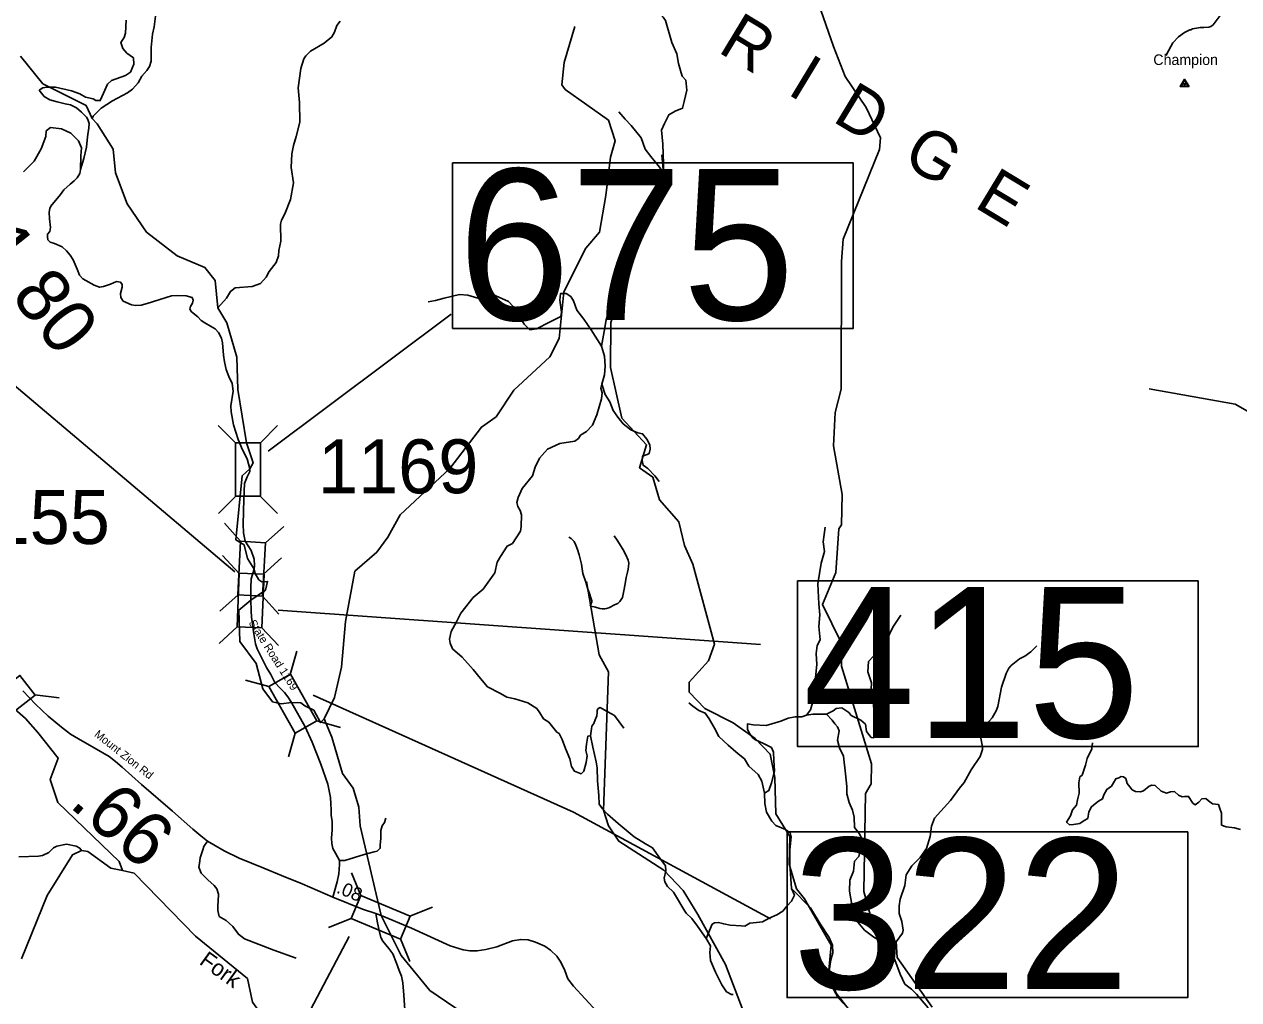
# Model space of a CAD drawing. Extents: x 1248089 to 1457196, y 820910 to 988753.
# Drawn here: x 1288997 to 1300259, y 874876 to 883926 of the extents above; entities that cross this region are included whole.
import ezdxf

# ---------------------------------------------------------------- set-up
doc = ezdxf.new("R2010")
doc.units = 0
for name, color, linetype in [('Exist Geographical Mountain Summit Label', 7, 'Continuous'), ('Exist Hydrographic Creek Single Shore', 7, 'Continuous'), ('Exist Hydrographic Misc Water Feature', 7, 'Continuous'), ('Exist Road Non-System Type 51', 7, 'Continuous'), ('Exist Road Secondary Structure Standard Bridge CELL', 7, 'Continuous'), ('Exist Road Secondary Structure Standard Bridge Number Label', 7, 'Continuous'), ('Exist Road Secondary Type 41 Attributed', 7, 'Continuous'), ('Exist Road Secondary Type 51 Attributed', 7, 'Continuous'), ('Exist Road Secondary Type 51 Label', 7, 'Continuous'), ('Exist Survey Geodetic Marker CELL', 7, 'Continuous'), ('Exist Survey Geodetic Marker Label', 7, 'Continuous'), ('Prop GRAU CAT1 Cell', 7, 'Continuous'), ('Prop Lane Lines', 7, 'Continuous'), ('Scratch_Level_4', 7, 'Continuous')]:
    doc.layers.add(name, color=color, linetype=linetype)

msp = doc.modelspace()

# ---------------------------------------------------------------- linework, layer by layer
at = {"layer": 'Exist Hydrographic Creek Single Shore'}
for points in [[(1291089, 879802), (1291119, 879858), (1291056, 880043), (1290977, 880537), (1290967, 880836), (1290875, 881156), (1290791, 881295), (1290768, 881549), (1290671, 881669), (1290415, 881776), (1290129, 881998), (1289952, 882261), (1289842, 882549), (1289822, 882766), (1289673, 883001), (1289627, 883052), (1289570, 883171), (1289170, 883373), (1288960, 883630)], [(1300406, 880298), (1300225, 880400), (1299427, 880544)], [(1291127, 878871), (1291067, 878970), (1291036, 879096), (1290959, 879142), (1291017, 879738), (1291089, 879802)], [(1291098, 878582), (1291235, 878677), (1291253, 878757), (1291199, 878753), (1291173, 878772), (1291137, 878830), (1291127, 878871)], [(1291475, 877634), (1291379, 877621), (1291298, 877641), (1291209, 877761), (1291148, 877996), (1290994, 878199), (1290985, 878491), (1291098, 878582)], [(1289908, 876074), (1289877, 876160), (1289307, 876706), (1289237, 876918), (1289312, 877116), (1289122, 877354), (1289009, 877484), (1288835, 877637)], [(1291777, 877481), (1291743, 877448), (1291681, 877561), (1291597, 877603), (1291562, 877632), (1291475, 877634)], [(1292306, 875658), (1292112, 876489), (1292099, 876663), (1292045, 876838), (1291948, 876975), (1291848, 877312), (1291777, 877481)], [(1292628, 873989), (1292480, 873916), (1292339, 873798), (1292149, 873939), (1291946, 874109), (1291864, 874236), (1291719, 874279), (1291609, 874359), (1291494, 874427), (1291324, 874630), (1291193, 874741), (1291112, 874855), (1291068, 875072), (1290585, 875466), (1290016, 876049), (1289908, 876074)], [(1293365, 874547), (1292758, 874963), (1292491, 875287), (1292306, 875658)]]:
    msp.add_lwpolyline(points, dxfattribs=at)
at = {"layer": 'Exist Hydrographic Misc Water Feature'}
for points in [[(1299587, 883637), (1299588, 883645), (1299647, 883755), (1299700, 883808), (1299757, 883848), (1299806, 883875), (1299814, 883875), (1299830, 883882), (1299903, 883896), (1299935, 883895), (1299983, 883900), (1299999, 883905), (1300021, 883921), (1300123, 884056), (1300181, 884106), (1300230, 884135), (1300279, 884171)], [(1290213, 884001), (1290202, 883901), (1290185, 883833), (1290172, 883709), (1290173, 883585), (1290157, 883535), (1290132, 883496), (1290087, 883445), (1290053, 883382), (1290000, 883323), (1289955, 883290), (1289815, 883217), (1289709, 883146), (1289635, 883072), (1289627, 883052)], [(1297415, 874807), (1297093, 875267), (1297083, 875412), (1296844, 875656), (1296783, 875880), (1296797, 876789), (1296849, 876880), (1296854, 877064), (1296576, 877972), (1296573, 878189), (1296398, 878544), (1296522, 878840), (1296549, 879246), (1296575, 879282), (1296582, 879564), (1296501, 880016), (1296517, 880324), (1296572, 880539), (1296576, 881724), (1296590, 881931), (1296927, 882765), (1296938, 882873), (1296803, 883154), (1296610, 883441), (1296500, 883719), (1296384, 884056)], [(1291925, 883956), (1291896, 883914), (1291874, 883854), (1291849, 883809), (1291778, 883750), (1291652, 883675), (1291607, 883632), (1291590, 883604), (1291560, 883517), (1291537, 883337), (1291548, 883199), (1291552, 883019), (1291518, 882884), (1291492, 882800), (1291478, 882723), (1291473, 882598), (1291494, 882454), (1291464, 882299), (1291413, 882166), (1291381, 882107), (1291372, 882071), (1291376, 881915), (1291356, 881827), (1291355, 881779), (1291333, 881717), (1291267, 881631), (1291240, 881579), (1291187, 881521), (1291110, 881493), (1290953, 881481), (1290909, 881447), (1290871, 881384), (1290791, 881295)], [(1291777, 877481), (1291874, 877679), (1291939, 877960), (1291975, 878386), (1292061, 878851), (1292266, 879027), (1292369, 879166), (1292483, 879374), (1292944, 879805), (1293236, 880189), (1293372, 880285), (1293537, 880531), (1293870, 880840), (1293957, 881012), (1294001, 881444), (1294203, 881848), (1294332, 881996), (1294390, 882336), (1294432, 882693), (1294477, 882843), (1294415, 883035), (1294014, 883322), (1293982, 883365), (1294003, 883572), (1294103, 883904)], [(1296712, 874700), (1296526, 874937), (1296456, 875115), (1296479, 875381), (1296231, 875812), (1296158, 875906), (1296089, 876134), (1296095, 876390), (1295967, 876602), (1295958, 876937), (1295914, 877155), (1295775, 877299), (1295571, 877444), (1295307, 877577), (1295161, 877731), (1295163, 877823), (1295343, 878020), (1295397, 878176), (1295198, 878916), (1295119, 879091), (1295066, 879309), (1294888, 879513), (1294826, 879724), (1294703, 879812), (1294767, 880024), (1294539, 880272), (1294434, 880743), (1294436, 881160), (1294671, 881904), (1294898, 882316), (1294935, 882440), (1294908, 882716)], [(1294774, 873878), (1294918, 873958), (1295020, 874057), (1295178, 874346), (1295603, 874686), (1295663, 874773), (1295499, 875203), (1295244, 875668), (1295107, 875891), (1294928, 876078), (1294510, 876346), (1294413, 876489), (1294367, 876634), (1294415, 877917), (1294327, 878076), (1294210, 878755)], [(1298387, 878160), (1298332, 878105), (1298275, 878064), (1298226, 878038), (1298148, 877976), (1298128, 877952), (1298103, 877903), (1298058, 877776), (1298025, 877596), (1298010, 877557), (1297973, 877491), (1297927, 877440), (1297877, 877358), (1297868, 877302), (1297884, 877221), (1297883, 877197), (1297862, 877132), (1297777, 877010), (1297714, 876890), (1297668, 876838), (1297587, 876724), (1297439, 876562), (1297411, 876486), (1297397, 876389), (1297362, 876278), (1297306, 876195), (1297228, 876119), (1297174, 876036), (1297162, 875937), (1297119, 875809), (1297109, 875747), (1297109, 875676), (1297135, 875603), (1297146, 875522), (1297141, 875495), (1297083, 875412)], [(1288947, 876202), (1289127, 876208), (1289167, 876215), (1289224, 876241), (1289267, 876286), (1289299, 876302), (1289388, 876319), (1289479, 876301), (1289511, 876282), (1289526, 876262)], [(1288971, 875255), (1289210, 875842), (1289445, 876221), (1289526, 876262), (1289587, 876251), (1289800, 876096), (1289908, 876074)]]:
    msp.add_lwpolyline(points, dxfattribs=at)
at = {"layer": 'Exist Road Non-System Type 51'}
for points in [[(1294736, 884371), (1294765, 884335), (1294809, 884261), (1294833, 884158), (1294848, 884072), (1294922, 883992), (1294942, 883960), (1295001, 883756), (1295048, 883651), (1295063, 883562), (1295081, 883497), (1295098, 883444), (1295131, 883406), (1295140, 883314), (1295116, 883208), (1295101, 883146), (1295033, 883119), (1294974, 883087), (1294933, 883004), (1294906, 882942), (1294918, 882815), (1294927, 882538)], [(1289134, 883315), (1289170, 883337), (1289207, 883342), (1289286, 883342), (1289434, 883309), (1289512, 883280), (1289565, 883251), (1289635, 883234), (1289660, 883218), (1289701, 883218), (1289730, 883288), (1289767, 883370), (1289804, 883403), (1289936, 883449), (1289981, 883482), (1290014, 883556), (1290010, 883613), (1289948, 883659), (1289911, 883700), (1289891, 883758), (1289924, 883803), (1289936, 883844), (1289940, 883964)], [(1294927, 882538), (1294886, 882601), (1294807, 882699), (1294753, 882767), (1294718, 882873), (1294624, 882988), (1294570, 883044), (1294511, 883115)], [(1288989, 882557), (1289088, 882656), (1289154, 882771), (1289195, 882886), (1289199, 882936), (1289240, 882969), (1289343, 882957), (1289429, 882915), (1289499, 882845), (1289528, 882779), (1289520, 882705), (1289519, 882578)], [(1294927, 882538), (1294922, 882442), (1294904, 882382), (1294857, 882264), (1294786, 882146), (1294647, 881981), (1294562, 881865), (1294538, 881827), (1294538, 881774), (1294535, 881726), (1294511, 881658), (1294503, 881548), (1294476, 881489), (1294452, 881400), (1294426, 881300), (1294393, 881185), (1294373, 881075), (1294349, 880940)], [(1294349, 880940), (1294255, 881090), (1294187, 881191), (1294122, 881273), (1294089, 881359), (1294066, 881400), (1294021, 881427), (1293968, 881427), (1293962, 881365), (1293980, 881256), (1293971, 881214), (1293868, 881161), (1293747, 881099), (1293685, 881090), (1293632, 881143), (1293531, 881309), (1293487, 881353), (1293342, 881418), (1293260, 881400), (1293204, 881386), (1293109, 881412), (1293032, 881418), (1292892, 881386), (1292809, 881362), (1292741, 881350)], [(1294349, 880940), (1294376, 880846), (1294382, 880755), (1294376, 880672), (1294352, 880586)], [(1294352, 880586), (1294344, 880551), (1294355, 880506), (1294349, 880450), (1294305, 880303), (1294267, 880208), (1294211, 880149), (1294155, 880113), (1294137, 880084), (1294101, 880057), (1293963, 880037), (1293848, 879983), (1293774, 879901), (1293735, 879818), (1293709, 879738), (1293615, 879620), (1293576, 879537), (1293564, 879490), (1293573, 879451), (1293594, 879416), (1293609, 879374), (1293606, 879268), (1293597, 879224), (1293523, 879109), (1293476, 879085), (1293414, 878987), (1293381, 878937), (1293361, 878837), (1293314, 878772), (1293252, 878686), (1293160, 878609), (1293045, 878461), (1293004, 878382), (1292954, 878292), (1292939, 878221), (1292945, 878185), (1292969, 878132), (1293057, 878055), (1293158, 877940), (1293228, 877857), (1293293, 877780), (1293414, 877718), (1293473, 877683), (1293547, 877668), (1293665, 877630), (1293751, 877577), (1293778, 877538), (1293813, 877482), (1293860, 877452), (1293936, 877357), (1293956, 877345), (1293986, 877289), (1294015, 877206), (1294057, 877111), (1294071, 877041), (1294098, 876996), (1294160, 876973), (1294187, 876996), (1294207, 877076), (1294216, 877138), (1294204, 877188), (1294210, 877247), (1294222, 877321), (1294249, 877324)], [(1294352, 880586), (1294385, 880491), (1294426, 880424), (1294458, 880342), (1294502, 880280), (1294552, 880218), (1294621, 880163), (1294687, 880134), (1294730, 880127), (1294769, 880077), (1294797, 880024), (1294801, 879985), (1294792, 879944), (1294774, 879935), (1294730, 879919), (1294726, 879880), (1294735, 879834), (1294778, 879806), (1294845, 879738), (1294884, 879683)], [(1296251, 877517), (1296288, 877567), (1296316, 877663), (1296322, 877732), (1296336, 877897), (1296346, 877986), (1296340, 878089), (1296350, 878161), (1296377, 878216), (1296364, 878339), (1296374, 878446), (1296364, 878549), (1296357, 878734), (1296388, 878926), (1296418, 879034), (1296405, 879123), (1296425, 879260)], [(1294245, 878526), (1294260, 878568), (1294260, 878576), (1294251, 878604), (1294238, 878645), (1294223, 878685), (1294204, 878749), (1294177, 878830), (1294163, 878918), (1294143, 879003), (1294128, 879053), (1294111, 879093), (1294095, 879126), (1294082, 879142), (1294068, 879154), (1294046, 879167)], [(1294245, 878526), (1294263, 878524), (1294283, 878520), (1294295, 878517), (1294335, 878507), (1294357, 878502), (1294379, 878502), (1294395, 878507), (1294419, 878513), (1294476, 878542), (1294500, 878551), (1294518, 878571), (1294545, 878608), (1294556, 878670), (1294570, 878736), (1294579, 878794), (1294590, 878844), (1294597, 878872), (1294601, 878896), (1294604, 878925), (1294596, 878954), (1294575, 879004), (1294550, 879051), (1294517, 879107), (1294496, 879140), (1294467, 879180)], [(1295860, 876794), (1295901, 876817), (1295925, 876889), (1295953, 876996), (1295949, 877099), (1295946, 877174), (1295925, 877215), (1295857, 877250), (1295771, 877291), (1295747, 877311), (1295719, 877353), (1295702, 877387), (1295702, 877435), (1295757, 877425), (1295877, 877421), (1296014, 877459), (1296080, 877487), (1296145, 877500), (1296207, 877500), (1296251, 877517), (1296309, 877524), (1296385, 877524), (1296436, 877524), (1296498, 877555), (1296526, 877579), (1296577, 877583), (1296642, 877541), (1296666, 877514), (1296755, 877469), (1296797, 877432), (1296807, 877366), (1296851, 877308), (1296875, 877307), (1296881, 877324), (1296899, 877355), (1296888, 877389), (1296875, 877461), (1296875, 877568), (1296868, 877643), (1296847, 877695), (1296854, 877815), (1296820, 877918), (1296827, 878014), (1296871, 878062), (1296943, 878103), (1296991, 878209), (1297050, 878333), (1297125, 878443)], [(1294249, 877324), (1294257, 877389), (1294260, 877413), (1294278, 877439), (1294290, 877472), (1294305, 877510), (1294308, 877540), (1294308, 877563), (1294319, 877578), (1294337, 877587), (1294373, 877566), (1294435, 877531), (1294470, 877513), (1294556, 877395)], [(1295860, 876794), (1295836, 876903), (1295802, 876965), (1295716, 877044), (1295675, 877112), (1295617, 877157), (1295524, 877239), (1295438, 877318), (1295397, 877397), (1295349, 877483), (1295311, 877535), (1295253, 877559), (1295198, 877600), (1295160, 877631)], [(1296436, 877524), (1296488, 877469), (1296512, 877435), (1296539, 877408), (1296553, 877370), (1296539, 877284), (1296556, 877212), (1296594, 877136), (1296611, 876972), (1296625, 876855), (1296625, 876786), (1296645, 876707), (1296676, 876635), (1296693, 876570), (1296697, 876474), (1296741, 876416), (1296762, 876374), (1296752, 876275), (1296735, 876206), (1296697, 876162), (1296687, 876069), (1296652, 875986), (1296649, 875883), (1296673, 875742), (1296690, 875643), (1296741, 875578), (1296789, 875523), (1296875, 875457), (1296944, 875416), (1297012, 875372), (1297043, 875320), (1297119, 875114), (1297163, 875021), (1297225, 874973), (1297270, 874929), (1297379, 874802)], [(1294249, 877324), (1294269, 877219), (1294299, 877083), (1294308, 877027), (1294313, 876906), (1294325, 876770), (1294328, 876690), (1294358, 876646), (1294405, 876598), (1294505, 876510), (1294653, 876386), (1294759, 876321), (1294824, 876285), (1294889, 876188), (1294942, 876117), (1294945, 876072), (1294931, 876005), (1294936, 875969), (1294963, 875928), (1295016, 875875), (1295121, 875699), (1295136, 875678), (1295186, 875631), (1295240, 875560), (1295319, 875445)], [(1300275, 876455), (1300219, 876470), (1300141, 876479), (1300100, 876496), (1300098, 876538), (1300098, 876606), (1300085, 876649), (1300071, 876686), (1300015, 876695), (1299979, 876722), (1299954, 876744), (1299916, 876739), (1299889, 876710), (1299855, 876683), (1299833, 876700), (1299794, 876763), (1299755, 876761), (1299734, 876759), (1299702, 876773), (1299663, 876807), (1299627, 876805), (1299588, 876793), (1299539, 876810), (1299484, 876863), (1299454, 876868), (1299428, 876856), (1299377, 876814), (1299348, 876805), (1299302, 876807), (1299272, 876822), (1299248, 876851), (1299224, 876882), (1299213, 876928), (1299191, 876945), (1299169, 876947), (1299148, 876935), (1299118, 876926), (1299099, 876889), (1299080, 876858), (1299036, 876828), (1299009, 876777), (1298997, 876739), (1298958, 876719), (1298932, 876697), (1298893, 876666), (1298869, 876620), (1298859, 876559), (1298827, 876539), (1298786, 876510), (1298728, 876503), (1298691, 876500), (1298662, 876522), (1298699, 876581), (1298718, 876637), (1298754, 876680), (1298764, 876731), (1298779, 876794), (1298776, 876887), (1298786, 876943), (1298808, 876960), (1298837, 877052), (1298852, 877113), (1298898, 877205), (1298902, 877258)], [(1295319, 875445), (1295376, 875576), (1295397, 875590), (1295435, 875593), (1295483, 875579), (1295544, 875569), (1295644, 875562), (1295678, 875559), (1295726, 875586), (1295788, 875593), (1295843, 875600), (1295905, 875634), (1295977, 875665), (1296032, 875699), (1296069, 875744), (1296110, 875789), (1296138, 875847), (1296110, 875909), (1296097, 876135), (1296097, 876266), (1296107, 876386), (1296100, 876424), (1296056, 876455), (1295966, 876492), (1295929, 876534), (1295881, 876616), (1295863, 876698), (1295860, 876794)], [(1291920, 876167), (1291970, 876168), (1292150, 876222), (1292242, 876248), (1292268, 876254), (1292298, 876281), (1292298, 876310), (1292304, 876375), (1292304, 876446), (1292316, 876490), (1292336, 876520), (1292351, 876561)], [(1290697, 876347), (1290663, 876299), (1290651, 876267), (1290628, 876193), (1290622, 876140), (1290616, 876107), (1290637, 876051), (1290699, 875989), (1290758, 875936), (1290781, 875906), (1290799, 875856), (1290796, 875791), (1290790, 875750), (1290790, 875705), (1290805, 875649), (1290870, 875611), (1290932, 875555), (1290982, 875484), (1291038, 875442), (1291310, 875336), (1291519, 875262)], [(1296596, 874838), (1296545, 874893), (1296501, 874974), (1296467, 875063), (1296460, 875145), (1296477, 875245), (1296494, 875310), (1296491, 875382), (1296460, 875454), (1296378, 875581), (1296288, 875729), (1296110, 875909), (1296138, 875847)], [(1295319, 875445), (1295361, 875377), (1295355, 875315), (1295361, 875241), (1295408, 875132), (1295464, 875014), (1295508, 874950), (1295555, 874926), (1295570, 874924)]]:
    msp.add_lwpolyline(points, dxfattribs=at)
at = {"layer": 'Exist Road Secondary Structure Standard Bridge CELL'}
for p, q in [((1290795, 880203), (1290955, 880043)), ((1291346, 880204), (1291186, 880043)), ((1290959, 879548), (1290799, 879387)), ((1291185, 879548), (1291346, 879388)), ((1290852, 879297), (1291003, 879129)), ((1291403, 879267), (1291234, 879116)), ((1290990, 878831), (1290836, 878998)), ((1291216, 878823), (1291382, 878977)), ((1290980, 878633), (1290811, 878482)), ((1291206, 878621), (1291357, 878452)), ((1290804, 878182), (1290970, 878336)), ((1291355, 878161), (1291201, 878327)), ((1291463, 877893), (1291523, 878111)), ((1291265, 877781), (1291047, 877842)), ((1289094, 877705), (1289319, 877676)), ((1291928, 877402), (1291710, 877463)), ((1291447, 877131), (1291508, 877349)), ((1292032, 876053), (1292117, 875843)), ((1292573, 875650), (1292783, 875735)), ((1291817, 875545), (1292027, 875630)), ((1292485, 875441), (1292571, 875231))]:
    msp.add_line(p, q, dxfattribs=at)
for points in [[(1291186, 880043), (1291187, 879548), (1290955, 879548), (1290955, 880043)], [(1291234, 879116), (1291207, 878621), (1290976, 878634), (1291003, 879129)], [(1290970, 878336), (1290989, 878832), (1291220, 878823), (1291201, 878327)], [(1291508, 877349), (1291265, 877781), (1291466, 877895), (1291710, 877463)], [(1288563, 877582), (1288956, 877885), (1289097, 877702), (1288704, 877399)], [(1292117, 875843), (1292574, 875651), (1292484, 875437), (1292027, 875630)]]:
    msp.add_lwpolyline(points, close=True, dxfattribs=at)
at = {"layer": 'Exist Road Secondary Structure Standard Bridge Number Label'}
for p, q in [((1290948, 878846), (1286961, 882217)), ((1291258, 879965), (1292954, 881236)), ((1291352, 878490), (1295825, 878171)), ((1292009, 875464), (1289936, 871537))]:
    msp.add_line(p, q, dxfattribs=at)
for points in [[(1292968, 882640), (1296684, 882640), (1296684, 881104), (1292968, 881104)], [(1296168, 878762), (1299884, 878762), (1299884, 877225), (1296168, 877225)], [(1296071, 876433), (1299787, 876433), (1299787, 874896), (1296071, 874896)]]:
    msp.add_lwpolyline(points, close=True, dxfattribs=at)
msp.add_lwpolyline([(1291676, 877703), (1294089, 876615), (1295918, 875628)], dxfattribs=at)
at = {"layer": 'Exist Road Secondary Type 41 Attributed'}
msp.add_lwpolyline([(1292258, 875676), (1292272, 875590), (1292287, 875518), (1292303, 875454), (1292323, 875419), (1292377, 875350), (1292413, 875301), (1292449, 875214), (1292473, 875146), (1292494, 875094), (1292506, 875032), (1292516, 874920), (1292529, 874735), (1292534, 874632), (1292542, 874550), (1292579, 874261), (1292593, 874150), (1292596, 874094), (1292596, 874035), (1292607, 874004), (1292628, 873989)], dxfattribs=at)
at = {"layer": 'Exist Road Secondary Type 51 Attributed'}
for points in [[(1289216, 881927), (1289211, 881953), (1289213, 881978), (1289233, 882004), (1289239, 882040), (1289231, 882120), (1289226, 882182), (1289233, 882218), (1289243, 882239), (1289331, 882347), (1289364, 882390), (1289421, 882442), (1289460, 882472), (1289488, 882501), (1289511, 882542), (1289519, 882578), (1289549, 882681), (1289573, 882786), (1289583, 882881), (1289595, 882966), (1289598, 883005), (1289585, 883042), (1289573, 883064), (1289526, 883111), (1289482, 883151), (1289426, 883177), (1289377, 883188), (1289300, 883206), (1289234, 883224), (1289180, 883257), (1289144, 883301), (1289134, 883315)], [(1291089, 879802), (1291065, 879895), (1291021, 879979), (1290980, 880073), (1290938, 880209), (1290916, 880329), (1290912, 880387), (1290933, 880521), (1290924, 880593), (1290895, 880659), (1290870, 880723), (1290853, 880793), (1290844, 880856), (1290834, 880969), (1290824, 881015), (1290799, 881065), (1290767, 881101), (1290724, 881125), (1290670, 881155), (1290638, 881179), (1290606, 881211), (1290546, 881259), (1290531, 881282), (1290539, 881309), (1290557, 881339), (1290563, 881367), (1290552, 881391), (1290498, 881405), (1290414, 881408), (1290363, 881405), (1290137, 881336), (1290082, 881321), (1290031, 881318), (1289992, 881324), (1289915, 881357), (1289892, 881391), (1289890, 881427), (1289903, 881488), (1289903, 881511), (1289890, 881532), (1289851, 881539), (1289795, 881516), (1289732, 881494), (1289695, 881486), (1289644, 881504), (1289541, 881563), (1289509, 881597), (1289486, 881655), (1289450, 881740), (1289423, 881784), (1289387, 881825), (1289349, 881861), (1289278, 881892), (1289237, 881905), (1289216, 881927)], [(1291127, 878871), (1291132, 878904), (1291127, 878963), (1291102, 879044), (1291044, 879130), (1291031, 879209), (1291026, 879289), (1291033, 879519), (1291038, 879665), (1291062, 879727), (1291088, 879778), (1291089, 879802)], [(1291098, 878582), (1291096, 878697), (1291102, 878781), (1291127, 878871)], [(1291475, 877634), (1291442, 877687), (1291411, 877726), (1291370, 877767), (1291321, 877819), (1291283, 877892), (1291242, 877958), (1291202, 878040), (1291156, 878130), (1291141, 878178), (1291125, 878271), (1291105, 878424), (1291101, 878483), (1291098, 878582)], [(1291859, 875829), (1291575, 875951), (1291381, 876030), (1291219, 876097), (1290989, 876191), (1290851, 876257), (1290755, 876313), (1290697, 876347), (1290635, 876396), (1290561, 876460), (1290372, 876625), (1290085, 876874), (1289903, 877035), (1289843, 877086), (1289784, 877134), (1289645, 877214), (1289498, 877296), (1289424, 877339), (1289342, 877404), (1289218, 877508), (1289101, 877618), (1288982, 877742)], [(1291859, 875829), (1291898, 875970), (1291915, 876044), (1291918, 876086), (1291921, 876132), (1291920, 876167), (1291882, 876235), (1291858, 876278), (1291848, 876324), (1291846, 876376), (1291851, 876452), (1291851, 876531), (1291843, 876587), (1291841, 876637), (1291840, 876693), (1291836, 876752), (1291812, 876875), (1291748, 877062), (1291666, 877266), (1291601, 877407), (1291475, 877634)], [(1292258, 875676), (1292132, 875716), (1291859, 875829)], [(1292306, 875658), (1292258, 875676)], [(1294305, 874766), (1294089, 875001), (1294038, 875070), (1294008, 875147), (1293973, 875226), (1293935, 875279), (1293876, 875336), (1293825, 875373), (1293738, 875411), (1293669, 875432), (1293601, 875436), (1293523, 875422), (1293379, 875366), (1293276, 875341), (1293198, 875331), (1293128, 875331), (1293068, 875339), (1292946, 875377), (1292589, 875540), (1292306, 875658)]]:
    msp.add_lwpolyline(points, dxfattribs=at)
at = {"layer": 'Exist Survey Geodetic Marker CELL'}
for points in [[(1299798, 883347), (1299757, 883416), (1299716, 883347)], [(1299790, 883351), (1299724, 883351), (1299757, 883407)], [(1299761, 883365), (1299761, 883374), (1299753, 883374), (1299753, 883365)]]:
    msp.add_lwpolyline(points, close=True, dxfattribs=at)

# ---------------------------------------------------------------- texts
at = {"layer": 'Exist Geographical Mountain Summit Label'}
msp.add_text('R  I  D  G  E', height=440, rotation=328.8202, dxfattribs=at).set_placement((1295417, 883675))
at = {"layer": 'Exist Road Secondary Structure Standard Bridge Number Label'}
for s, p in [('675', (1293018, 881183)), ('415', (1296218, 877304)), ('322', (1296121, 874975))]:
    msp.add_text(s, height=1400, dxfattribs=at).set_placement(p)
at = {"layer": 'Exist Road Secondary Type 51 Label'}
for s, rotation, p in [('State Road 1169', 302.4691, (1291074, 878372)), ('Mount Zion Rd', 321.5794, (1289640, 877326))]:
    msp.add_text(s, height=75, rotation=rotation, dxfattribs=at).set_placement(p)
at = {"layer": 'Exist Survey Geodetic Marker Label'}
msp.add_text('Champion', height=98.4, dxfattribs=at).set_placement((1299467, 883548))
at = {"layer": 'Prop GRAU CAT1 Cell'}
for s, height, rotation, p in [('1.80', 500, 308.4174, (1288517, 881840)), ('.66', 500, 319.0006, (1289401, 876676)), ('.08', 125, 337.5045, (1291884, 875871))]:
    msp.add_text(s, height=height, rotation=rotation, dxfattribs=at).set_placement(p)
at = {"layer": 'Prop Lane Lines'}
for s, p in [('1169', (1291720, 879575)), ('1155', (1288303, 879104))]:
    msp.add_text(s, height=500, dxfattribs=at).set_placement(p)
at = {"layer": 'Scratch_Level_4'}
msp.add_text('Fork', height=150, rotation=324.2019, dxfattribs=at).set_placement((1290611, 875213))

doc.saveas('drawing.dxf')
